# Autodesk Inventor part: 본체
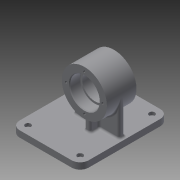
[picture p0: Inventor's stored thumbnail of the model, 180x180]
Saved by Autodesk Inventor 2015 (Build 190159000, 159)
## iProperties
Created: 2019-09
Part Number: 본체
Material: 일반
Document SubType Name: Modeling
Designer: now
Density: 1 g/cm^3
Appearance: 기본값
Author: now
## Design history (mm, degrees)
sketch "스케치1"
  geometry: L1 (-49, 63)-(49, 63); L2 (49, 63)-(49, -63); L3 (49, -63)-(-49, -63); L4 (-49, -63)-(-49, 63); L5 (-49, 63)-(49, -63); L6 (49, 63)-(-49, -63); 1 further point
  constraints: 12 end point, 2 midpoint, 2 parallel, 1 horizontal, 1 perpendicular
  dimensions: "d0" = 98 distance of L2.end L3.end; "d1" = 126 distance of L1.end L2.end
extrude "돌출1" new body sketch "스케치1" distance "d2" = 9; taper "d3" = 0 deg
fillet "모깎기1" dims "d4" = 12
sketch "스케치2"
  geometry: A1 r 12 centre (-37, 51) between (-37, 63) and (-49, 51) reference; A2 r 12 centre (-37, -51) between (-49, -51) and (-37, -63) reference; A3 r 12 centre (37, -51) between (37, -63) and (49, -51) reference; A4 r 12 centre (37, 51) between (49, 51) and (37, 63) reference; 1 further point
hole "구멍1" sketch "스케치2" at (-37, -51), (-37, 51), (37, -51), (37, 51) diameter "d5" = 4.5; stored, may be unused: countersink angle "d9" = 90 deg, drill point angle "d11" = 118 deg; dims "d6" = 6, "d7" = 8, "d8" = 4.4, "d10" = 8
sketch "스케치3"
  geometry: L1 (-49, 51)-(-49, -51) reference; L2 (45, 4)-(-19, 4); L3 (-19, 4)-(-19, -4); L4 (-19, -4)-(45, -4); L5 (45, -4)-(45, 4); L6 (45, 4)-(-19, -4); L7 (-19, 4)-(45, -4); 3 further points
  constraints: 12 end point, 3 midpoint, 2 parallel, 1 horizontal, 1 horizontal alignment, 1 perpendicular
  dimensions: "d22" = 8 distance of L2.end L3.end; "d23" = 62 distance from line of L1 point (13, 0); "d24" = 64 distance of L3.end L4.end
extrude "돌출2" join sketch "스케치3" distance "d15" = 50; taper "d16" = 0 deg
sketch "스케치4"
  geometry: L1 (-49, 51)-(-49, -51) reference; L2 (9, -17)-(17, -17); L3 (17, -17)-(17, 17); L4 (17, 17)-(9, 17); L5 (9, 17)-(9, -17); L6 (9, -17)-(17, 17); L7 (17, -17)-(9, 17); 3 further points
  constraints: 12 end point, 3 midpoint, 2 parallel, 1 horizontal, 1 horizontal alignment, 1 perpendicular
  dimensions: "d17" = 8 distance of L3.end L4.end; "d18" = 62 distance from line of L1 point (13, 0); "d19" = 34 distance of L2.end L3.end
extrude "돌출3" join sketch "스케치4" distance "d20" = 50; taper "d21" = 0 deg
sketch "스케치6"
  geometry: L1 (49, 9)-(49, 0) reference; L2 (49, 0)-(-49, 0) reference; L3 (-49, 0)-(-49, 9) reference; L4 (-49, 9)-(-45, 9) reference; L5 (-45, 9)-(-45, 59) reference; L6 (-45, 59)-(19, 59) reference; L7 (19, 59)-(19, 9) reference; L8 (19, 9)-(49, 9) reference; C1 r 32 at (-13, 59); 1 further point
  constraints: 1 centre point
  dimensions: "d25" = 64 diameter of C1; "d26" = 59 distance from line of L2 C1.centre; "d27" = 36 horizontal distance of L2.end C1.centre
extrude "돌출4" join sketch "스케치6" stored distance "d28" = 42; taper "d29" = 0 deg
sketch "스케치7"
  geometry: C1 r 32 at (0, 0) reference; C2 r 21 at (0, 0); 1 further point
  constraints: 1 centre point, 1 coincident
  dimensions: "d30" = 42 diameter of C2
extrude "돌출5" cut sketch "스케치7" distance "d31" = 15; taper "d32" = 0 deg
fillet "모깎기2" dims "d33" = 3
fillet "모깎기3" dims "d34" = 3
sketch "스케치8"
  geometry: C1 r 21 at (0, 0) reference; C2 r 18 at (0, 0); 1 further point
  constraints: 1 centre point, 1 coincident
  dimensions: "d35" = 36 diameter of C2
extrude "돌출6" cut sketch "스케치8" stored distance "d36" = 15; taper "d37" = 0 deg
sketch "스케치9"
  geometry: C1 r 32 at (0, 0) reference; C2 r 21 at (0, 0); 1 further point
  constraints: 1 centre point, 1 coincident
  dimensions: "d38" = 42 diameter of C2
extrude "돌출7" cut sketch "스케치9" distance "d39" = 15; taper "d40" = 0 deg
fillet "모깎기4" dims "d41" = 0.3
chamfer "모따기1" distance "d42" = 1; stored, may be unused: second distance "d43" = 2, angle "d44" = 45 deg
sketch "스케치10"
  geometry: C1 r 32 at (0, 0) reference; 2 further points
  constraints: 1 vertical alignment
  dimensions: "d45" = 26 distance of C1.centre point (0, 26)
hole "구멍2" sketch "스케치10" at (0, 26) diameter "d46" = 3.242; stored, may be unused: countersink angle "d50" = 90 deg, drill point angle "d52" = 118 deg; dims "d47" = 8, "d48" = 8, "d49" = 4.4, "d51" = 10
node "솔리드1"
pattern_circular "원형 패턴1" dims angle "d54" = 360 deg
mirror "대칭1"
node "절단 모서리 투영1"
